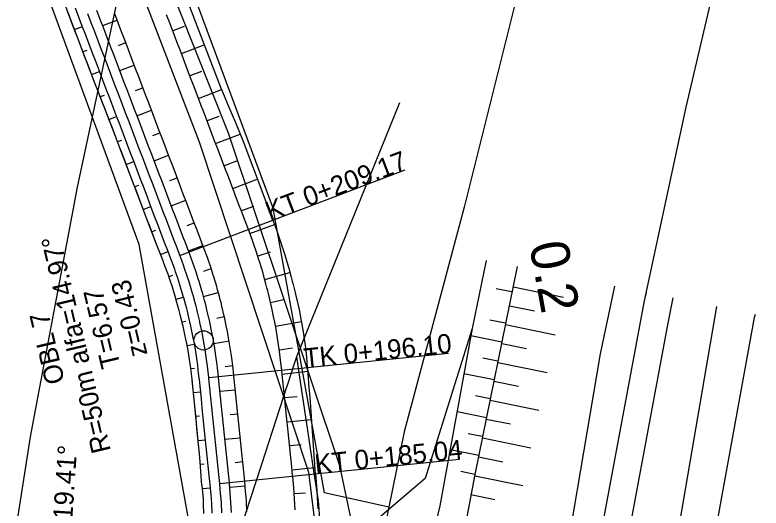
# Model space of a CAD drawing. Extents: x -583721 to -583071, y -1166145 to -1165065.
# Drawn here: x -583433.1 to -583355.7, y -1165470.9 to -1165419.8 of the extents above; entities that cross this region are included whole.
import ezdxf

# ---------------------------------------------------------------- set-up
doc = ezdxf.new("R2010")
doc.units = 0
for name, color, linetype in [('01_DOPRAVA', 7, 'Continuous'), ('03_PC_POPIS_NAVRH', 7, 'Continuous'), ('13', 7, 'Continuous'), ('14', 7, 'Continuous'), ('21', 7, 'Continuous'), ('_Rozpiska', 7, 'Continuous'), ('Kabel_navrh', 7, 'Continuous'), ('KOTY', 7, 'Continuous'), ('North Arrow', 7, 'Continuous'), ('Popis PP', 7, 'Continuous'), ('Ram HC5', 7, 'Continuous'), ('Rámy', 7, 'Continuous'), ('TISK', 7, 'Continuous'), ('Trojúhelniky', 7, 'Continuous')]:
    doc.layers.add(name, color=color, linetype=linetype)

msp = doc.modelspace()

# ---------------------------------------------------------------- linework, layer by layer
at = {"layer": '01_DOPRAVA'}
for points in [[(-583327.43, -1165211.57), (-583327.59, -1165214.21), (-583330.92, -1165226.21), (-583336.19, -1165245.95), (-583345.5, -1165278.93), (-583352.15, -1165304.95), (-583359.3, -1165333.07), (-583366.57, -1165360.34), (-583373.53, -1165387.37), (-583380.03, -1165413.66), (-583386.52, -1165439.72), (-583392.75, -1165463.03), (-583394.35, -1165470.85)], [(-583394.35, -1165470.85), (-583401.02, -1165469.37), (-583406.34, -1165439.81), (-583441.73, -1165344.5), (-583443.26, -1165334.4), (-583448.82, -1165319.07), (-583454.83, -1165307.19)], [(-583415.62, -1165476.12), (-583415.02, -1165472.65), (-583420.22, -1165443.6), (-583448.97, -1165365.39), (-583458.92, -1165347.2), (-583477.78, -1165313.78)], [(-583394.35, -1165470.85), (-583397.05, -1165483.9), (-583399.8, -1165518.65), (-583400, -1165542.33), (-583402.51, -1165559.81), (-583402.19, -1165563.54), (-583409.42, -1165564.02), (-583405.3, -1165586.77), (-583405.42, -1165638.41)]]:
    msp.add_lwpolyline(points, dxfattribs=at)
at = {"layer": '03_PC_POPIS_NAVRH'}
for points in [[(-583461.59, -1165302.25), (-583452.7, -1165330.11), (-583439.53, -1165361.89), (-583424.49, -1165398.09), (-583411.01, -1165432.01), (-583399.44, -1165466.53), (-583397.85, -1165474.11)], [(-583464.75, -1165303.13), (-583454.71, -1165331.15), (-583441.76, -1165362.61), (-583427, -1165399.08), (-583414.01, -1165432.94), (-583402.68, -1165467.21), (-583401.88, -1165473.68), (-583399.3, -1165487.37), (-583400.15, -1165499.25), (-583403.33, -1165538.26), (-583407.25, -1165561.02), (-583404.58, -1165574.64), (-583401.09, -1165602.76), (-583401.09, -1165613.37), (-583400.94, -1165621.86)]]:
    msp.add_lwpolyline(points, dxfattribs=at)
at = {"layer": '13'}
msp.add_lwpolyline([(-583409.781, -1165473.366), (-583407.515, -1165466.397), (-583405.251, -1165459.434), (-583404.9, -1165458.355), (-583404.84, -1165458.171), (-583404.048, -1165455.735), (-583403.873, -1165455.197), (-583393.188, -1165428.841)], dxfattribs=at)
at = {"layer": '14'}
for p, q in [((-583424.009, -1165420.875), (-583422.513, -1165420.306)), ((-583426.945, -1165421.269), (-583426.118, -1165420.955)), ((-583415.557, -1165420.97), (-583416.74, -1165421.42)), ((-583422.372, -1165422.927), (-583421.624, -1165422.642)), ((-583415.851, -1165423.756), (-583413.476, -1165422.853)), ((-583425.642, -1165423.448), (-583426.054, -1165423.605)), ((-583422.231, -1165425.548), (-583420.735, -1165424.979)), ((-583425.164, -1165425.941), (-583424.34, -1165425.628)), ((-583413.77, -1165425.639), (-583414.962, -1165426.093)), ((-583420.594, -1165427.6), (-583419.846, -1165427.315)), ((-583414.073, -1165428.429), (-583411.676, -1165427.517)), ((-583423.859, -1165428.12), (-583424.266, -1165428.275)), ((-583420.453, -1165430.221), (-583418.957, -1165429.652)), ((-583423.361, -1165430.605), (-583422.562, -1165430.301)), ((-583411.951, -1165430.297), (-583413.184, -1165430.766)), ((-583418.816, -1165432.273), (-583418.068, -1165431.989)), ((-583412.295, -1165433.103), (-583409.751, -1165432.135)), ((-583422.065, -1165432.787), (-583422.457, -1165432.936)), ((-583418.675, -1165434.894), (-583417.179, -1165434.325)), ((-583421.571, -1165435.274), (-583420.784, -1165434.974)), ((-583410.13, -1165434.954), (-583411.406, -1165435.439)), ((-583417.038, -1165436.946), (-583416.29, -1165436.662)), ((-583410.517, -1165437.776), (-583407.975, -1165436.809)), ((-583420.292, -1165437.462), (-583420.688, -1165437.613)), ((-583416.897, -1165439.567), (-583415.401, -1165438.998)), ((-583419.805, -1165439.952), (-583419.006, -1165439.648)), ((-583408.361, -1165439.631), (-583409.628, -1165440.112)), ((-583415.26, -1165441.619), (-583414.512, -1165441.335)), ((-583408.742, -1165442.45), (-583406.2, -1165441.528)), ((-583418.516, -1165442.136), (-583418.914, -1165442.287)), ((-583415.119, -1165444.241), (-583413.617, -1165443.688)), ((-583418.02, -1165444.616), (-583417.228, -1165444.321)), ((-583406.63, -1165444.395), (-583407.922, -1165444.812)), ((-583413.522, -1165446.347), (-583412.761, -1165446.097)), ((-583416.755, -1165446.799), (-583417.142, -1165446.931)), ((-583407.207, -1165447.207), (-583404.593, -1165446.487)), ((-583413.561, -1165448.99), (-583412.019, -1165448.566)), ((-583416.403, -1165449.277), (-583415.619, -1165449.053)), ((-583405.27, -1165449.326), (-583406.596, -1165449.631)), ((-583415.386, -1165451.564), (-583415.776, -1165451.653)), ((-583412.176, -1165451.241), (-583411.395, -1165451.068)), ((-583406.088, -1165452.079), (-583403.403, -1165451.583)), ((-583415.255, -1165454.058), (-583414.495, -1165453.923)), ((-583412.476, -1165453.868), (-583410.899, -1165453.597)), ((-583404.34, -1165454.358), (-583405.689, -1165454.546)), ((-583414.496, -1165456.443), (-583414.872, -1165456.492)), ((-583411.317, -1165456.24), (-583410.523, -1165456.14)), ((-583405.396, -1165457.029), (-583402.759, -1165456.738)), ((-583411.846, -1165458.827), (-583410.255, -1165458.661)), ((-583414.603, -1165458.959), (-583413.851, -1165458.879)), ((-583403.844, -1165459.383), (-583405.141, -1165459.516)), ((-583413.974, -1165461.405), (-583414.351, -1165461.444)), ((-583410.795, -1165461.232), (-583409.999, -1165461.151)), ((-583404.886, -1165462.003), (-583402.379, -1165461.746)), ((-583414.101, -1165463.931), (-583413.341, -1165463.853)), ((-583411.336, -1165463.801), (-583409.744, -1165463.638)), ((-583403.416, -1165464.365), (-583404.631, -1165464.49)), ((-583413.486, -1165466.381), (-583413.886, -1165466.422)), ((-583410.285, -1165466.207), (-583409.489, -1165466.126)), ((-583404.376, -1165466.977), (-583402.013, -1165466.749)), ((-583413.668, -1165468.899), (-583412.834, -1165468.828)), ((-583410.831, -1165468.775), (-583409.236, -1165468.64)), ((-583402.969, -1165469.385), (-583404.15, -1165469.466))]:
    msp.add_line(p, q, dxfattribs=at)
at = {"layer": '21'}
for points in [[(-583422.559, -1165399.251), (-583411.784, -1165427.249), (-583411.41, -1165428.177), (-583411.024, -1165429.1), (-583410.248, -1165430.945), (-583409.859, -1165431.867), (-583409.484, -1165432.794), (-583407.724, -1165437.474), (-583407.372, -1165438.41), (-583406.377, -1165441.06), (-583406.303, -1165441.25), (-583405.882, -1165442.381), (-583405.768, -1165442.702), (-583405.487, -1165443.52), (-583405.213, -1165444.363), (-583405.118, -1165444.669), (-583404.774, -1165445.825), (-583404.713, -1165446.042), (-583404.458, -1165446.989), (-583404.354, -1165447.395), (-583404.263, -1165447.734), (-583404.154, -1165448.156), (-583403.87, -1165449.329), (-583403.846, -1165449.435), (-583403.613, -1165450.508), (-583403.484, -1165451.149), (-583403.382, -1165451.692), (-583403.18, -1165452.875), (-583403.179, -1165452.881), (-583403.003, -1165454.075), (-583402.933, -1165454.609), (-583402.869, -1165455.274), (-583402.788, -1165456.355), (-583402.783, -1165456.456), (-583402.7, -1165457.453), (-583402.613, -1165458.449), (-583402.53, -1165459.446), (-583402.333, -1165462.442), (-583402.261, -1165463.44), (-583402.039, -1165466.433), (-583401.96, -1165467.389), (-583401.955, -1165467.437), (-583401.84, -1165468.631), (-583401.793, -1165469.228), (-583401.753, -1165469.827), (-583401.694, -1165471.025)], [(-583413.51, -1165471.514), (-583413.539, -1165470.552), (-583413.561, -1165470.07), (-583413.589, -1165469.589), (-583413.699, -1165468.632), (-583413.724, -1165468.595), (-583413.802, -1165467.639), (-583413.94, -1165465.643), (-583414.029, -1165464.647), (-583414.53, -1165459.672), (-583414.632, -1165458.677), (-583414.746, -1165457.581), (-583414.843, -1165456.72), (-583414.911, -1165456.19), (-583414.971, -1165455.764), (-583415.12, -1165454.81), (-583415.121, -1165454.805), (-583415.291, -1165453.861), (-583415.376, -1165453.428), (-583415.483, -1165452.916), (-583415.675, -1165452.06), (-583415.695, -1165451.975), (-583415.929, -1165451.04), (-583416.018, -1165450.703), (-583416.092, -1165450.433), (-583416.176, -1165450.108), (-583416.382, -1165449.352), (-583416.431, -1165449.179), (-583416.707, -1165448.256), (-583416.783, -1165448.012), (-583417.002, -1165447.339), (-583417.227, -1165446.685), (-583417.319, -1165446.428), (-583417.659, -1165445.527), (-583417.718, -1165445.375), (-583418.025, -1165444.603), (-583418.386, -1165443.67), (-583419.457, -1165440.868), (-583419.812, -1165439.933), (-583422.285, -1165433.384), (-583422.644, -1165432.451), (-583424.455, -1165427.79), (-583424.815, -1165426.857), (-583428.021, -1165418.448)], [(-583412.65, -1165471.479), (-583412.701, -1165470.5), (-583412.733, -1165470.01), (-583412.77, -1165469.523), (-583412.86, -1165468.547), (-583412.864, -1165468.507), (-583412.962, -1165467.553), (-583413.064, -1165466.558), (-583413.166, -1165465.563), (-583413.268, -1165464.568), (-583413.37, -1165463.574), (-583413.472, -1165462.579), (-583413.574, -1165461.584), (-583413.676, -1165460.589), (-583413.778, -1165459.595), (-583413.88, -1165458.6), (-583413.982, -1165457.605), (-583413.992, -1165457.504), (-583414.09, -1165456.629), (-583414.158, -1165456.091), (-583414.217, -1165455.657), (-583414.364, -1165454.688), (-583414.365, -1165454.683), (-583414.53, -1165453.722), (-583414.612, -1165453.282), (-583414.715, -1165452.76), (-583414.9, -1165451.888), (-583414.92, -1165451.802), (-583415.143, -1165450.848), (-583415.229, -1165450.504), (-583415.299, -1165450.228), (-583415.386, -1165449.898), (-583415.597, -1165449.129), (-583415.647, -1165448.954), (-583415.928, -1165448.015), (-583416.005, -1165447.766), (-583416.227, -1165447.081), (-583416.453, -1165446.416), (-583416.544, -1165446.154), (-583416.881, -1165445.234), (-583416.939, -1165445.079), (-583417.235, -1165444.302), (-583417.59, -1165443.368), (-583417.946, -1165442.433), (-583418.302, -1165441.498), (-583418.657, -1165440.564), (-583419.013, -1165439.629), (-583419.368, -1165438.694), (-583419.724, -1165437.76), (-583420.08, -1165436.825), (-583420.435, -1165435.891), (-583420.791, -1165434.956), (-583421.146, -1165434.021), (-583421.502, -1165433.087), (-583421.858, -1165432.152), (-583422.213, -1165431.217), (-583422.569, -1165430.283), (-583422.924, -1165429.348), (-583423.28, -1165428.413), (-583423.636, -1165427.479), (-583423.991, -1165426.544), (-583424.347, -1165425.61), (-583424.702, -1165424.675), (-583425.058, -1165423.74), (-583425.414, -1165422.806), (-583425.769, -1165421.871), (-583426.125, -1165420.936), (-583426.48, -1165420.002), (-583426.836, -1165419.067)], [(-583410.652, -1165471.396), (-583410.704, -1165470.377), (-583410.738, -1165469.868), (-583410.777, -1165469.36), (-583410.87, -1165468.344), (-583410.874, -1165468.303), (-583410.972, -1165467.349), (-583411.074, -1165466.354), (-583411.176, -1165465.359), (-583411.278, -1165464.364), (-583411.38, -1165463.37), (-583411.482, -1165462.375), (-583411.584, -1165461.38), (-583411.686, -1165460.385), (-583411.788, -1165459.39), (-583411.89, -1165458.396), (-583411.992, -1165457.401), (-583412.003, -1165457.3), (-583412.104, -1165456.389), (-583412.175, -1165455.829), (-583412.237, -1165455.378), (-583412.389, -1165454.369), (-583412.39, -1165454.364), (-583412.562, -1165453.364), (-583412.648, -1165452.905), (-583412.755, -1165452.362), (-583412.948, -1165451.455), (-583412.968, -1165451.365), (-583413.201, -1165450.372), (-583413.29, -1165450.014), (-583413.363, -1165449.727), (-583413.453, -1165449.384), (-583413.673, -1165448.584), (-583413.725, -1165448.401), (-583414.017, -1165447.423), (-583414.098, -1165447.165), (-583414.328, -1165446.452), (-583414.564, -1165445.759), (-583414.659, -1165445.487), (-583415.009, -1165444.529), (-583415.07, -1165444.367), (-583415.366, -1165443.591), (-583415.721, -1165442.656), (-583416.077, -1165441.722), (-583416.432, -1165440.787), (-583416.788, -1165439.852), (-583417.144, -1165438.918), (-583417.499, -1165437.983), (-583417.855, -1165437.049), (-583418.21, -1165436.114), (-583418.566, -1165435.179), (-583418.922, -1165434.245), (-583419.277, -1165433.31), (-583419.633, -1165432.375), (-583419.988, -1165431.441), (-583420.344, -1165430.506), (-583420.7, -1165429.571), (-583421.055, -1165428.637), (-583421.411, -1165427.702), (-583421.766, -1165426.768), (-583422.122, -1165425.833), (-583422.478, -1165424.898), (-583422.833, -1165423.964), (-583423.189, -1165423.029), (-583423.544, -1165422.094), (-583423.9, -1165421.16), (-583424.256, -1165420.225), (-583424.611, -1165419.29)], [(-583413.51, -1165471.514), (-583413.539, -1165470.552), (-583413.561, -1165470.07), (-583413.589, -1165469.589), (-583413.699, -1165468.632), (-583413.724, -1165468.595), (-583413.802, -1165467.639), (-583413.871, -1165466.641), (-583413.94, -1165465.643), (-583414.029, -1165464.647), (-583414.129, -1165463.652), (-583414.229, -1165462.657), (-583414.329, -1165461.662), (-583414.429, -1165460.667), (-583414.53, -1165459.672), (-583414.632, -1165458.677), (-583414.735, -1165457.682), (-583414.746, -1165457.581), (-583414.843, -1165456.72), (-583414.911, -1165456.19), (-583414.971, -1165455.764), (-583415.12, -1165454.81), (-583415.121, -1165454.805), (-583415.291, -1165453.861), (-583415.376, -1165453.428), (-583415.483, -1165452.916), (-583415.675, -1165452.06), (-583415.695, -1165451.975), (-583415.929, -1165451.04), (-583416.018, -1165450.703), (-583416.092, -1165450.433), (-583416.176, -1165450.108), (-583416.382, -1165449.352), (-583416.431, -1165449.179), (-583416.707, -1165448.256), (-583416.783, -1165448.012), (-583417.002, -1165447.339), (-583417.227, -1165446.685), (-583417.319, -1165446.428), (-583417.659, -1165445.527), (-583417.718, -1165445.375), (-583418.025, -1165444.603), (-583418.386, -1165443.67), (-583418.743, -1165442.736), (-583419.1, -1165441.802), (-583419.457, -1165440.868), (-583419.812, -1165439.933), (-583420.166, -1165438.998), (-583420.519, -1165438.062), (-583420.872, -1165437.127), (-583421.225, -1165436.191), (-583421.578, -1165435.256), (-583421.932, -1165434.32), (-583422.285, -1165433.384), (-583422.644, -1165432.451), (-583423.006, -1165431.519), (-583423.368, -1165430.587), (-583423.73, -1165429.655), (-583424.092, -1165428.723), (-583424.455, -1165427.79), (-583424.815, -1165426.857), (-583425.171, -1165425.923), (-583425.527, -1165424.989), (-583425.883, -1165424.054), (-583426.24, -1165423.12), (-583426.596, -1165422.185), (-583426.952, -1165421.251), (-583427.308, -1165420.317), (-583427.665, -1165419.382)], [(-583409.053, -1165471.33), (-583409.107, -1165470.279), (-583409.142, -1165469.754), (-583409.182, -1165469.23), (-583409.278, -1165468.182), (-583409.283, -1165468.14), (-583409.381, -1165467.185), (-583409.483, -1165466.191), (-583409.585, -1165465.196), (-583409.687, -1165464.201), (-583409.789, -1165463.206), (-583409.891, -1165462.212), (-583409.993, -1165461.217), (-583410.095, -1165460.222), (-583410.197, -1165459.227), (-583410.299, -1165458.232), (-583410.401, -1165457.238), (-583410.411, -1165457.137), (-583410.516, -1165456.197), (-583410.589, -1165455.62), (-583410.653, -1165455.154), (-583410.81, -1165454.114), (-583410.811, -1165454.108), (-583410.988, -1165453.077), (-583411.077, -1165452.604), (-583411.187, -1165452.044), (-583411.386, -1165451.108), (-583411.406, -1165451.015), (-583411.646, -1165449.991), (-583411.738, -1165449.622), (-583411.814, -1165449.326), (-583411.907, -1165448.972), (-583412.134, -1165448.147), (-583412.188, -1165447.958), (-583412.489, -1165446.95), (-583412.572, -1165446.684), (-583412.81, -1165445.948), (-583413.052, -1165445.234), (-583413.151, -1165444.953), (-583413.512, -1165443.965), (-583413.575, -1165443.798), (-583413.87, -1165443.022), (-583414.226, -1165442.087), (-583414.581, -1165441.153), (-583414.937, -1165440.218), (-583415.293, -1165439.284), (-583415.648, -1165438.349), (-583416.004, -1165437.414), (-583416.359, -1165436.48), (-583416.715, -1165435.545), (-583417.071, -1165434.61), (-583417.426, -1165433.676), (-583417.782, -1165432.741), (-583418.137, -1165431.806), (-583418.493, -1165430.872), (-583418.849, -1165429.937), (-583419.204, -1165429.003), (-583419.56, -1165428.068), (-583419.915, -1165427.133), (-583420.271, -1165426.199), (-583420.627, -1165425.264), (-583420.982, -1165424.329), (-583421.338, -1165423.395), (-583421.693, -1165422.46), (-583422.049, -1165421.525), (-583422.405, -1165420.591), (-583422.76, -1165419.656)], [(-583404.058, -1165471.123), (-583404.117, -1165469.973), (-583404.155, -1165469.397), (-583404.199, -1165468.823), (-583404.304, -1165467.676), (-583404.309, -1165467.63), (-583404.407, -1165466.675), (-583404.509, -1165465.681), (-583404.611, -1165464.686), (-583404.713, -1165463.691), (-583404.815, -1165462.696), (-583404.917, -1165461.701), (-583405.019, -1165460.707), (-583405.121, -1165459.712), (-583405.223, -1165458.717), (-583405.325, -1165457.722), (-583405.427, -1165456.728), (-583405.437, -1165456.626), (-583405.552, -1165455.598), (-583405.632, -1165454.965), (-583405.702, -1165454.456), (-583405.874, -1165453.317), (-583405.875, -1165453.31), (-583406.069, -1165452.181), (-583406.166, -1165451.663), (-583406.287, -1165451.05), (-583406.504, -1165450.025), (-583406.527, -1165449.923), (-583406.79, -1165448.802), (-583406.89, -1165448.398), (-583406.973, -1165448.073), (-583407.075, -1165447.686), (-583407.324, -1165446.782), (-583407.383, -1165446.576), (-583407.712, -1165445.472), (-583407.803, -1165445.18), (-583408.064, -1165444.375), (-583408.33, -1165443.592), (-583408.437, -1165443.285), (-583408.832, -1165442.203), (-583408.902, -1165442.02), (-583409.197, -1165441.244), (-583409.553, -1165440.309), (-583409.908, -1165439.375), (-583410.264, -1165438.44), (-583410.619, -1165437.506), (-583410.975, -1165436.571), (-583411.331, -1165435.636), (-583411.686, -1165434.702), (-583412.042, -1165433.767), (-583412.397, -1165432.832), (-583412.753, -1165431.898), (-583413.109, -1165430.963), (-583413.464, -1165430.028), (-583413.82, -1165429.094), (-583414.175, -1165428.159), (-583414.531, -1165427.225), (-583414.887, -1165426.29), (-583415.242, -1165425.355), (-583415.598, -1165424.421), (-583415.953, -1165423.486), (-583416.309, -1165422.551), (-583416.665, -1165421.617), (-583417.02, -1165420.682), (-583417.376, -1165419.747)]]:
    msp.add_lwpolyline(points, dxfattribs=at)
at = {"layer": '_Rozpiska'}
for points in [[(-583381.61, -1165448.51), (-583383.2, -1165448.18)], [(-583381.43, -1165447.98), (-583376.23, -1165449.04)], [(-583381.83, -1165449.94), (-583379.24, -1165450.47)], [(-583382.23, -1165451.77), (-583383.85, -1165451.44)], [(-583382.23, -1165451.9), (-583377.07, -1165452.95)], [(-583382.62, -1165453.73), (-583385.83, -1165453.08)], [(-583382.63, -1165453.86), (-583380.06, -1165454.38)], [(-583383.02, -1165455.69), (-583384.6, -1165455.37)], [(-583383.03, -1165455.82), (-583377.91, -1165456.86)], [(-583383.42, -1165457.65), (-583386.54, -1165457.02)], [(-583383.43, -1165457.78), (-583380.88, -1165458.3)], [(-583383.81, -1165459.61), (-583385.36, -1165459.3)], [(-583383.83, -1165459.74), (-583378.76, -1165460.77)], [(-583384.21, -1165461.57), (-583387.26, -1165460.95)], [(-583384.23, -1165461.7), (-583381.7, -1165462.21)], [(-583384.61, -1165463.53), (-583386.11, -1165463.23)], [(-583384.62, -1165463.66), (-583379.6, -1165464.68)], [(-583385, -1165465.49), (-583387.97, -1165464.89)], [(-583385.02, -1165465.62), (-583382.52, -1165466.13)], [(-583385.4, -1165467.45), (-583386.86, -1165467.15)], [(-583385.42, -1165467.58), (-583380.44, -1165468.59)], [(-583385.82, -1165469.54), (-583383.34, -1165470.04)]]:
    msp.add_lwpolyline(points, dxfattribs=at)
at = {"layer": 'Kabel_navrh'}
for points in [[(-583384.25, -1165445.233), (-583385.69, -1165452.31)], [(-583385.69, -1165452.31), (-583390.55, -1165467.88), (-583397.85, -1165474.11)]]:
    msp.add_lwpolyline(points, dxfattribs=at)
at = {"layer": 'KOTY'}
msp.add_lwpolyline([(-583411.651, -1165471.437), (-583411.702, -1165470.439), (-583411.736, -1165469.939), (-583411.774, -1165469.441), (-583411.865, -1165468.446), (-583411.869, -1165468.405), (-583411.967, -1165467.451), (-583412.069, -1165466.456), (-583412.171, -1165465.461), (-583412.273, -1165464.466), (-583412.375, -1165463.472), (-583412.477, -1165462.477), (-583412.579, -1165461.482), (-583412.681, -1165460.487), (-583412.783, -1165459.492), (-583412.885, -1165458.498), (-583412.987, -1165457.503), (-583412.998, -1165457.402), (-583413.097, -1165456.509), (-583413.167, -1165455.96), (-583413.227, -1165455.517), (-583413.377, -1165454.529), (-583413.378, -1165454.523), (-583413.546, -1165453.543), (-583413.63, -1165453.093), (-583413.735, -1165452.561), (-583413.924, -1165451.672), (-583413.944, -1165451.583), (-583414.172, -1165450.61), (-583414.259, -1165450.259), (-583414.331, -1165449.977), (-583414.419, -1165449.641), (-583414.635, -1165448.856), (-583414.686, -1165448.677), (-583414.972, -1165447.719), (-583415.052, -1165447.466), (-583415.278, -1165446.767), (-583415.508, -1165446.087), (-583415.602, -1165445.821), (-583415.945, -1165444.881), (-583416.005, -1165444.723), (-583416.3, -1165443.947), (-583416.656, -1165443.012), (-583417.011, -1165442.077), (-583417.367, -1165441.143), (-583417.723, -1165440.208), (-583418.078, -1165439.273), (-583418.434, -1165438.339), (-583418.789, -1165437.404), (-583419.145, -1165436.47), (-583419.501, -1165435.535), (-583419.856, -1165434.6), (-583420.212, -1165433.666), (-583420.567, -1165432.731), (-583420.923, -1165431.796), (-583421.279, -1165430.862), (-583421.634, -1165429.927), (-583421.99, -1165428.992), (-583422.345, -1165428.058), (-583422.701, -1165427.123), (-583423.057, -1165426.189), (-583423.412, -1165425.254), (-583423.768, -1165424.319), (-583424.123, -1165423.385), (-583424.479, -1165422.45), (-583424.835, -1165421.515), (-583425.19, -1165420.581), (-583425.546, -1165419.646)], dxfattribs=at)
at = {"layer": 'North Arrow'}
msp.add_lwpolyline([(-583406.29, -1165537.631), (-583405.45, -1165531.231), (-583402.899, -1165511.794), (-583401.556, -1165501.557), (-583401.145, -1165498.427), (-583400.859, -1165496.251), (-583400.148, -1165490.833), (-583400.317, -1165488.478), (-583400.383, -1165487.572), (-583400.447, -1165486.676), (-583400.511, -1165485.783), (-583400.992, -1165479.096), (-583401.073, -1165477.96), (-583401.248, -1165475.533), (-583401.362, -1165473.946), (-583401.377, -1165473.734), (-583401.468, -1165472.472), (-583401.631, -1165470.205), (-583402.096, -1165467.088), (-583402.861, -1165461.972), (-583403.655, -1165456.655), (-583403.873, -1165455.197)], dxfattribs=at)
at = {"layer": 'Popis PP'}
for points in [[(-583453.882, -1165797.966), (-583451.761, -1165745.072), (-583447.631, -1165643.262), (-583446.859, -1165623.987), (-583445.813, -1165599.542), (-583444.662, -1165577.371), (-583442.034, -1165542.78), (-583439.667, -1165520.038), (-583436.68, -1165496.549), (-583431.494, -1165463.535), (-583426.631, -1165437.638), (-583422.051, -1165416.223), (-583417.441, -1165396.545), (-583410.087, -1165367.405), (-583389.989, -1165290.805), (-583376.799, -1165240.446), (-583367.037, -1165203.237), (-583351.367, -1165143.48), (-583345.203, -1165119.977)], [(-583393.93, -1165800.36), (-583391.81, -1165747.49), (-583389.84, -1165698.95), (-583387.68, -1165645.68), (-583386.91, -1165626.47), (-583385.88, -1165602.38), (-583384.78, -1165581.2), (-583382.27, -1165548.16), (-583380.06, -1165526.93), (-583377.27, -1165504.99), (-583372.36, -1165473.73), (-583367.8, -1165449.45), (-583363.5, -1165429.34), (-583359.14, -1165410.73), (-583351.98, -1165382.36), (-583344.08, -1165352.25), (-583331.95, -1165306.02), (-583318.76, -1165255.66), (-583309, -1165218.46), (-583293.33, -1165158.7), (-583283.823, -1165122.453)], [(-583389.634, -1165693.877), (-583387.68, -1165645.68), (-583386.91, -1165626.47), (-583385.88, -1165602.38), (-583384.78, -1165581.2), (-583382.27, -1165548.16), (-583380.06, -1165526.93), (-583377.27, -1165504.99), (-583372.36, -1165473.73), (-583367.8, -1165449.45), (-583367.613, -1165448.577)]]:
    msp.add_lwpolyline(points, dxfattribs=at)
at = {"layer": 'Ram HC5'}
msp.add_lwpolyline([(-583360.341, -1165450.038), (-583367.18, -1165490.03), (-583370.52, -1165513.34), (-583372.57, -1165531.94)], dxfattribs=at)
at = {"layer": 'Rámy'}
for points in [[(-583381.01, -1165445.884), (-583385.4, -1165467.45), (-583386.25, -1165471.86), (-583389.24, -1165488.68)], [(-583387.97, -1165575.42), (-583386.01, -1165549.07), (-583381.4, -1165510.93), (-583377.18, -1165483.31), (-583372.38, -1165454.92), (-583370.88, -1165447.92)], [(-583381.17, -1165566.96), (-583378.46, -1165539.97), (-583374.22, -1165502.22), (-583370.96, -1165481.8), (-583365.4, -1165451.92), (-583364.832, -1165449.136)], [(-583356.354, -1165450.84), (-583356.44, -1165451.15), (-583363.59, -1165490.55), (-583367.66, -1165516.72), (-583368.63, -1165520.98)], [(-583385.69, -1165452.31), (-583389.03, -1165470.72), (-583393.16, -1165487.97), (-583398.62, -1165539.99), (-583394.89, -1165613.24), (-583393.56, -1165631.64)]]:
    msp.add_lwpolyline(points, dxfattribs=at)
at = {"layer": 'TISK'}
for points in [[(-583416.005, -1165444.723), (-583392.639, -1165435.833)], [(-583412.998, -1165457.402), (-583388.128, -1165454.851)], [(-583411.869, -1165468.405), (-583387, -1165465.854)]]:
    msp.add_lwpolyline(points, dxfattribs=at)
at = {"layer": 'Trojúhelniky'}
msp.add_circle((-583413.546, -1165453.543), 1, dxfattribs=at)

# ---------------------------------------------------------------- texts
at = {"layer": 'TISK'}
for s, height, rotation, p in [('KT 0+209.17', 2, 20.83038, (-583406.658, -1165441.167)), ('R=50m alfa=14.97%%d', 2, 103.34307, (-583423.147, -1165464.988)), ('0.2', 4, 280.32301, (-583379.782, -1165443.597)), ('   z=0.43', 2, 103.34307, (-583418.838, -1165457.157)), ('  T=6.57', 2, 103.34307, (-583421.811, -1165457.62)), ('OBL 7', 2, 103.34307, (-583427.927, -1165457.832)), ('TK 0+196.10', 2, 5.85577, (-583403.05, -1165456.382)), ('KT 0+185.04', 2, 5.85577, (-583401.921, -1165467.385)), ('R=50m alfa=19.41%%d', 2, 86.14994, (-583428.197, -1165487.506))]:
    msp.add_text(s, height=height, rotation=rotation, dxfattribs=at).set_placement(p)

doc.saveas('drawing.dxf')
